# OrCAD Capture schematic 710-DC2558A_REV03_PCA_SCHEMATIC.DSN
size Custom; note: 36V BATTERY CHARGER AND BACKUP MANAGER
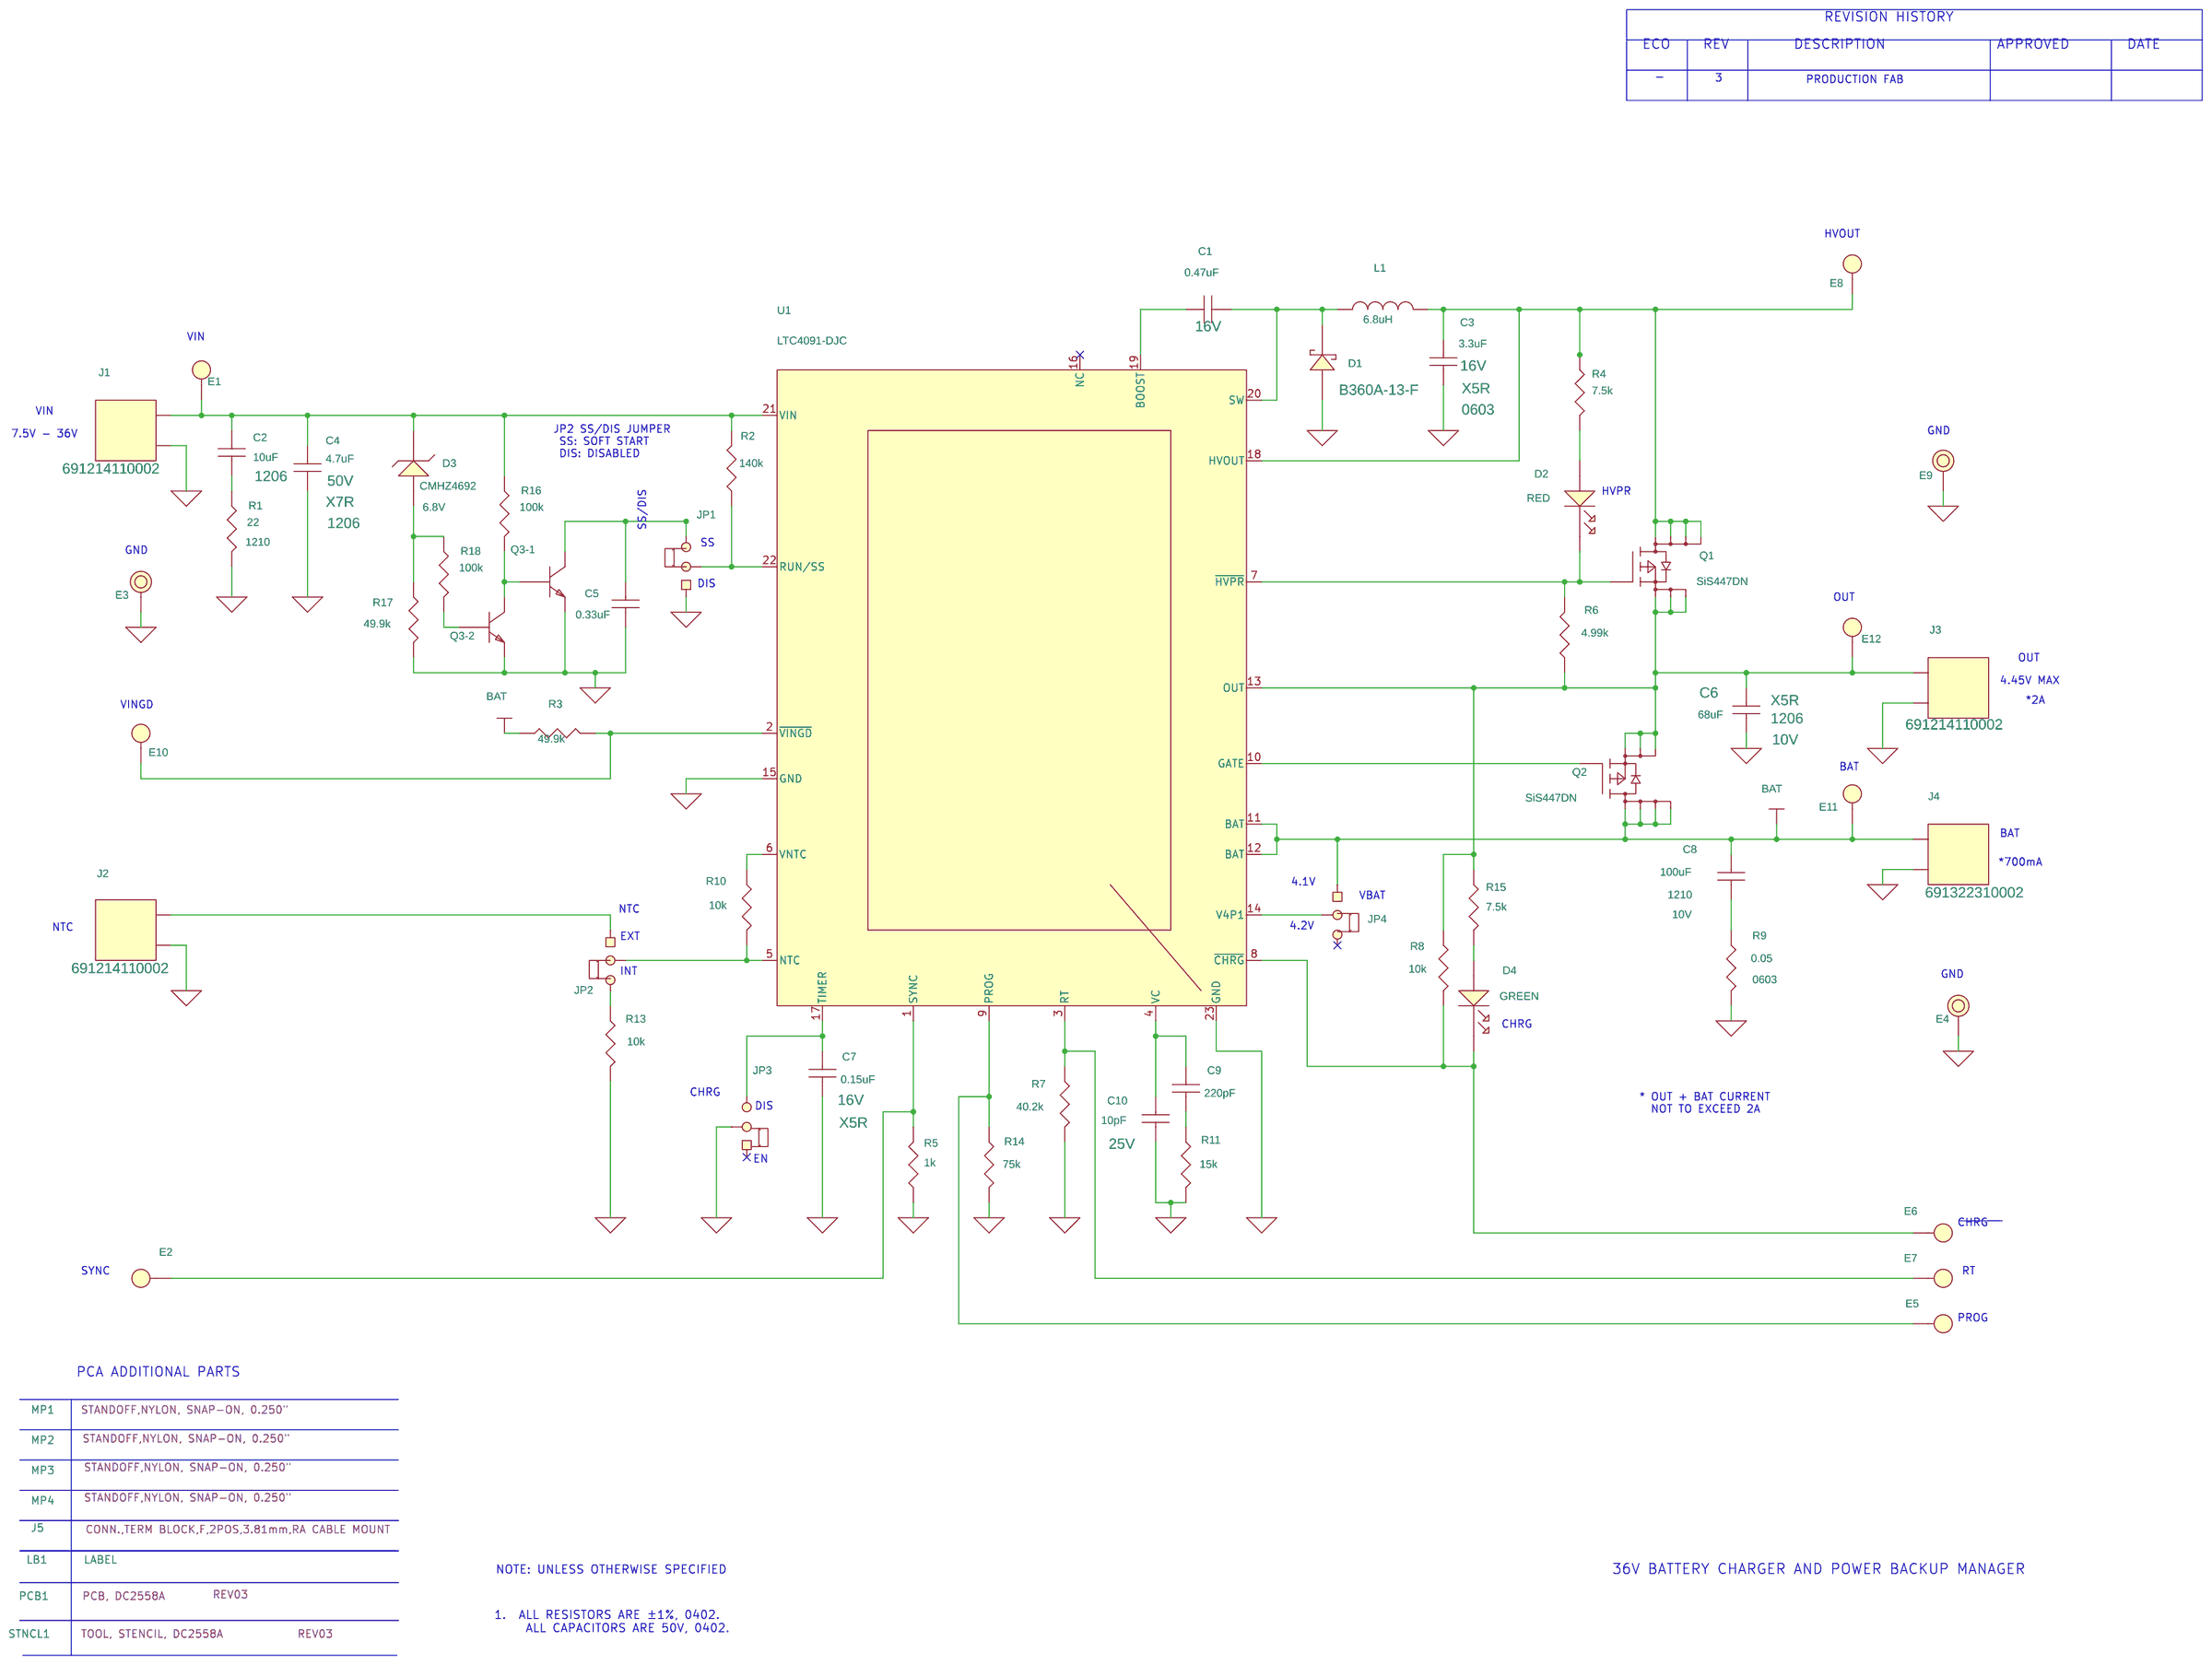
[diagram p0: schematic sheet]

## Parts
C1  0.47uF  [CC0402N]
C2  10uF  [CC1206N]
C3  3.3uF  [CC0603N]
C4  4.7uF  [CC1206N]
C5  0.33uF  [CC0805N]
C6  68uF  [CC1206N]
C7  0.15uF  [CC0402N]
C8  100uF  [CC1210M]
C9  220pF  [CC0402N]
C10  10pF  [CC0402N]
D1  DIODE_SCHOTTKY_A_ALT  [SMA-N]
D2  RED  [LED-WURTH-WL-SMCW]
D3  CMHZ4692  [SOD-123M]
D4  GREEN  [LED-WURTH-WL-SMCW]
E1  TEST POINT  [MILLMAX2308]
E2  TEST POINT  [MILLMAX2308]
E3  TEST POINT  [MILLMAX2501]
E4  TEST POINT  [MILLMAX2501]
E5  TEST POINT  [MILLMAX2308]
E6  TEST POINT  [MILLMAX2308]
E7  TEST POINT  [MILLMAX2308]
E8  TEST POINT  [MILLMAX2308]
E9  TEST POINT  [MILLMAX2501]
E10  TEST POINT  [MILLMAX2308]
E11  TEST POINT  [MILLMAX2308]
E12  TEST POINT  [MILLMAX2308]
J1  TERMINAL BLOCK  [TERM_BLK-WURTH-691214110002]
J2  TERMINAL BLOCK  [TERM_BLK-WURTH-691214110002]
J3  TERMINAL BLOCK  [TERM_BLK-WURTH-691214110002]
J4  SHROUDED HEADER  [WURTH-691322310002]
J5  TERM BLOCK
JP1  HDR  [HD1X3-079]
JP2  HDR  [HD1X3-079]
JP3  HDR  [HD1X3-079]
JP4  HDR  [HD1X3-079]
L1  6.8uH  [IND-XAL40XX]
LB1  LABEL  [895-0154_REV01]
MP1  STANDOFF  [MTG-8831]
MP2  STANDOFF  [MTG-8831]
MP3  STANDOFF  [MTG-8831]
MP4  STANDOFF  [MTG-8831]
PCB1  PCB, DC2558A
Q1  SiS447DN  [POWERPAK1212-8S]
Q2  SiS447DN  [POWERPAK1212-8S]
Q3  MMDT5551  [DIODESINC-SOT363]  (sections -1,-2)
R1  22  [CR1210N]
R2  140k  [CR0402N]
R3  49.9k  [CR0402N]
R4  7.5k  [CR0402N]
R5  1k  [CR0402N]
R6  4.99k  [CR0402N]
R7  40.2k  [CR0402N]
R8  10k  [CR0402N]
R9  0.05  [CR0603M]
R10  10k  [CR0402N]
R11  15k  [CR0402N]
R13  10k  [CR0402N]
R14  75k  [CR0402N]
R15  7.5k  [CR0402N]
R16  100k  [CR0402N]
R17  49.9k  [CR0402N]
R18  100k  [CR0402N]
STNCL1  TOOL, STENCIL, 700-DC2558A
U1  LTC4091-DJC  [LTC-DJC-22-1714]
XJP1  SHUNT
XJP2  SHUNT
XJP3  SHUNT
XJP4  SHUNT

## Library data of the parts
C1 = CAP: CAP.,0.47uF,X5R,16V,10%,0402; CLASS: DISCRETE; Dielectric Type: X5R; FPLIST: CC0402N,CC0402L,CC0402M; Manufacturer: TAIYO YUDEN; Manufacturer PN: EMK105ABJ474KV-F; PART_NUMBER: 150-3431; Package Size: 0402; Rated Voltage: 16V; Tolerance: 10%
C2 = CAP: CAP.,10uF,X5R,50V,10%,1206; CLASS: DISCRETE; Dielectric Type: X5R; FPLIST: CC1206N,CC1206L,CC1206M; Manufacturer: MURATA; Manufacturer PN: GRM31CR61H106KA12L; PART_NUMBER: 150-0330; Package Size: 1206; Rated Voltage: 50V; Tolerance: 10%
C3 = CAP: CAP.,3.3uF,X5R,16V,10%,0603; CLASS: DISCRETE; Dielectric Type: X5R; Manufacturer: TDK; Manufacturer PN: C1608X5R1C335K080AC; PART_NUMBER: 150-3529; Package Size: 0603; Rated Voltage: 16V; Tolerance: 10%
C4 = CAP: CAP.,4.7uF,X7R,50V,10%,1206; CLASS: DISCRETE; Dielectric Type: X7R; Manufacturer: AVX; Manufacturer PN: 12065C475KAT2A; PART_NUMBER: 150-0334; Package Size: 1206; Package Type: SMD; Rated Voltage: 50V; Tolerance: 10%
C5 = CAP: CAP.,0.33uF,X7R,50V,10%,0805; CLASS: DISCRETE; Dielectric Type: X7R; Manufacturer: MURATA; Manufacturer PN: GCM219R71H334KA55D; PART_NUMBER: 150-0600; Package Size: 0805; Rated Voltage: 50V; Tolerance: 10%
C6 = CAP: CAP.,68uF,X5R,10V,20%,1206; CLASS: DISCRETE; Dielectric Type: X5R; Manufacturer: TDK; Manufacturer PN: C3216X5R1A686M160AC; PART_NUMBER: 150-0601; Package Size: 1206; Package Type: SMD; Rated Voltage: 10V; Tolerance: 20%
C7 = CAP: CAP.,0.15uF,X5R,16V,+/-20%,0402; CLASS: DISCRETE; Dielectric Type: X5R; Manufacturer: TDK; Manufacturer PN: C1005X5R1C154M050BB; PART_NUMBER: 150-0602; Package Size: 0402; Rated Voltage: 16V; Tolerance: +/-20%
C8 = CAP: CAP.,100uF,X5R,10V,20%,1210; CLASS: DISCRETE; Dielectric Type: X5R; FPLIST: CC1210N,CC1210L,CC1210M; Manufacturer: MURATA; Manufacturer PN: GRM32ER61A107ME20L; PART_NUMBER: 150-3207; Package Size: 1210; Rated Voltage: 10V; Tolerance: 20%
C9 = CAP: CAP.,220pF,C0G,50V,5%,0402; CLASS: DISCRETE; Dielectric Type: C0G; Manufacturer: AVX; Manufacturer PN: 04025A221JAT2A; PART_NUMBER: 150-2013; Package Size: 0402; Rated Voltage: 50V; Tolerance: 5%
C10 = CAP: CAP.,10pF,NP0,25V,10%,0402; CLASS: DISCRETE; Dielectric Type: NP0; Manufacturer: AVX; Manufacturer PN: 04023A100KAT2A; PART_NUMBER: 150-3187; Package Size: 0402; Rated Voltage: 25V; Tolerance: 10%
D1 = DIODE_SCHOTTKY_A_ALT: DIODE,SCHOTTKY RECTIFIER,60V,3A,4.6mm X 2.92mm; CLASS: DISCRETE; Manufacturer: DIODES INC.; Manufacturer PN: B360A-13-F; PART_NUMBER: 210-0103; Rated Voltage: 60V
D2 = LED_ALT: LED,RED,WATERCLEAR,1206; CLASS: DISCRETE; FPLIST: LED_1206,LED-WURTH-WL-SMCW; Manufacturer: WURTH ELEKTRONIK; Manufacturer PN: 150120RS75000; PART_NUMBER: 270-0078
D3 = ZENER_DIODE_ALT: DIODE,ZENER,6.8V,500mW,SOD-123; CLASS: DISCRETE; FPLIST: SOD-123N, SOD-123M; Manufacturer: CENTRAL SEMI; Manufacturer PN: CMHZ4692 BK Lead Free; PART_NUMBER: 210-0252; Rated Voltage: 6.8V
D4 = LED_ALT: LED,GREEN,WATERCLEAR,1206; CLASS: DISCRETE; FPLIST: LED_1206,LED-WURTH-WL-SMCW; Manufacturer: WURTH ELEKTRONIK; Manufacturer PN: 150120GS75000; PART_NUMBER: 270-0080
E1 E2 E5-E8 E10-E12 = TEST_POINT_.156_MILL-MAX_2308: TEST POINT,TURRET,0.064",MTG. HOLE; CLASS: IO; Manufacturer: MILL-MAX; Manufacturer PN: 2308-2-00-80-00-00-07-0; PART_NUMBER: 260-0004
E3 E4 E9 = TESTPOINT_.219_MILL-MAX_2501: TEST POINT,TURRET,0.094",MTG. HOLE; CLASS: IO; Manufacturer: MILL-MAX; Manufacturer PN: 2501-2-00-80-00-00-07-0; PART_NUMBER: 260-0003
J1-J3 = 2P_TERMINAL_BLOCK_3.5MM: CONN.,TERMINAL BLOCK,1x2,3.5mm,THT; CLASS: IO; Manufacturer: WURTH ELEKTRONIK; Manufacturer PN: 691214110002; PART_NUMBER: 250-0587
J4 = 2P_TERMINAL_BLOCK_3.5MM: CONN.,SHROUDED HEADER,1x2,3.81mm,THT; CLASS: IO; Manufacturer: WURTH ELEKTRONIK; Manufacturer PN: 691322310002; PART_NUMBER: 250-0690
J5 = BLANK_PINLESS_MECHANICAL_PART: CONN.,TERM BLOCK,F,2POS,3.81mm,RA CABLE MOUNT; CLASS: IO; Manufacturer: WURTH ELEKTRONIK; Manufacturer PN: 691361300002; PART_NUMBER: 250-0691
JP1-JP4 = 3_PIN_HEADER_.079_SINGLE_ROW_D: CONN.,HDR,MALE,1x3,2mm,THT, STR; CLASS: IO; Manufacturer: Wurth Elektronik; Manufacturer PN: 62000311121; PART_NUMBER: 250-0484
L1 = IND_ALT: IND.,6.8uH,PWR,20%,3.9A,74.1mOHMS,SMD 4x4mm; CLASS: DISCRETE; Manufacturer: COILCRAFT; Manufacturer PN: XAL4030-682MEC; PART_NUMBER: 200-0207; Package Size: SMD 4x4mm; Tolerance: 20%
LB1 = BLANK_LABEL: LABEL SPEC, DEMO BOARD SERIAL NUMBER; Manufacturer: BRADY; Manufacturer PN: THT-96-717-10; PART_NUMBER: 895-0154
MP1-MP4 = BLANK_MECHANICAL_PART: STANDOFF,NYLON, SNAP-ON, 0.250"; CLASS: MECHANICAL PART; Manufacturer: KEYSTONE; Manufacturer PN: 8831; PART_NUMBER: 763-0006
PCB1 = BLANK_PCB_PART: BOM Notes: REV03; CLASS: PCB; Manufacturer: EAGLE ELECTRONICS, INC; Manufacturer PN: 600-DC2558A; PART_NUMBER: 600-DC2558A
Q1 Q2 = SiS447DN: XSTR.,MOSFET P-CHAN,20V,17A,8-pin PowerPAK 1212; CLASS: DISCRETE; Manufacturer: VISHAY; Manufacturer PN: SIS447DN-T1-GE3; PART_NUMBER: 240-0200; Package Size: 3.33mmx3.33mm; Package Type: 8-pin PowerPAK 1212
Q3 = MMDT5551_SOT-363_ALT: XSTR.,GP BJT NPN,160V,0.2A,SOT-363; CLASS: DISCRETE; Manufacturer: DIODES, INC.; Manufacturer PN: MMDT5551-7-F; PART_NUMBER: 240-0261; Package Size: SOT-363; Package Type: SOT-363
R1 = RES: RES.,22 OHMS,1%,1/2W,1210; CLASS: DISCRETE; Manufacturer: VISHAY; Manufacturer PN: CRCW121022R0FKEA; PART_NUMBER: 100-2045; Package Size: 1210; Rated Power: 1/2W; Temperature Coefficient: 100PPM; Tolerance: 1%
R2 = RES: RES.,140k OHMS,1%,1/16W,0402; CLASS: DISCRETE; Manufacturer: VISHAY; Manufacturer PN: CRCW0402140KFKED; PART_NUMBER: 100-2880; Package Size: 0402; Rated Power: 1/16W; Temperature Coefficient: 100ppm; Tolerance: 1%
R3 R17 = RES: RES.,49.9k OHMS,1%,1/16W,0402; CLASS: DISCRETE; Manufacturer: NIC; Manufacturer PN: NRC04F4992TRF; PART_NUMBER: 100-2406; Package Size: 0402; Rated Power: 1/16W; Temperature Coefficient: 100ppm/C; Tolerance: 1%
R4 R15 = RES: RES.,7.5k OHMS,10%,1/16W,0402; CLASS: DISCRETE; FPLIST: CR0402N,CR0402L,CR0402M; Manufacturer: VISHAY; Manufacturer PN: CRCW04027K50FKED; PART_NUMBER: 100-2038; Package Size: 0402; Rated Power: 1/16W; Temperature Coefficient: 100+/-; Tolerance: 10%
R5 = RES: RES.,1k OHM,1%,1/16W,0402; CLASS: DISCRETE; Manufacturer: VISHAY; Manufacturer PN: CRCW04021K00FKED; PART_NUMBER: 100-2456; Package Size: 0402; Rated Power: 1/16W; Temperature Coefficient: 100ppm/C; Tolerance: 1%
R6 = RES: RES.,AEC-Q200,4.99k OHMS,1%,1/10W,0402; CLASS: DISCRETE; Manufacturer: PANASONIC; Manufacturer PN: ERJ2RKF4991X; PART_NUMBER: 100-2409; Package Size: 0402; Rated Power: 1/10W; Temperature Coefficient: 100ppm/C; Tolerance: 1%
R7 = RES: RES.,40.2k OHMS,1%,1/16W,0402; CLASS: DISCRETE; Manufacturer: NIC; Manufacturer PN: NRC04F4022TRF; PART_NUMBER: 100-0296; Package Size: 0402; Rated Power: 1/16W; Temperature Coefficient: 100ppm; Tolerance: 1%
R8 = RES: RES.,10k OHMS,1%,1/16W,0402; CLASS: DISCRETE; FPLIST: CR0402N,CR0402L,CR0402M; Manufacturer: VISHAY; Manufacturer PN: CRCW040210K0FKED; PART_NUMBER: 100-2545; Package Size: 0402; Rated Power: 1/16W; Temperature Coefficient: 100ppm/C; Tolerance: 1%
R9 = RES: RES.,AEC-Q200,0.05 OHMS,1%,1/4W,0603; CLASS: DISCRETE; FPLIST: CR0603N,CR0603L,CR0603M; Manufacturer: SUSMU; Manufacturer PN: RL0816S-R050-F; PART_NUMBER: 100-0808; Package Size: 0603; Rated Power: 1/4W; Temperature Coefficient: +/-100PPM; Tolerance: 1%
R10 R13 = RES: RES.,10k OHMS,1%,1/16W,0402; CLASS: DISCRETE; Manufacturer: VISHAY; Manufacturer PN: CRCW040210K0FKED; PART_NUMBER: 100-2545; Package Size: 0402; Rated Power: 1/16W; Temperature Coefficient: 100ppm/C; Tolerance: 1%
R11 = RES: RES.,15k OHMS,1%,1/16W,0402; CLASS: DISCRETE; Manufacturer: NIC; Manufacturer PN: NRC04F1502TRF; PART_NUMBER: 100-2315; Package Size: 0402; Rated Power: 1/16W; Temperature Coefficient: 100ppm/C; Tolerance: 1%
R14 = RES: RES.,75k OHMS,1%,1/16W,0402; CLASS: DISCRETE; Manufacturer: VISHAY; Manufacturer PN: CRCW040275K0FKED; PART_NUMBER: 100-0536; Package Size: 0402; Rated Power: 1/16W; Temperature Coefficient: 100ppm; Tolerance: 1%
R16 R18 = RES: RES.,100k OHMS,1%,1/16W,0402; CLASS: DISCRETE; Manufacturer: VISHAY; Manufacturer PN: CRCW0402100KFKED; PART_NUMBER: 100-2396; Package Size: 0402; Rated Power: 1/16W; Temperature Coefficient: 100ppm; Tolerance: 1%
STNCL1 = BLANK_STENCIL_PART: TOOL, STENCIL, DC2558A; BOM Notes: REV03; CLASS: DISCRETE; Manufacturer: LINEAR TECHNOLOGY; Manufacturer PN: 830-DC2558A; PART_NUMBER: 830-2558A
U1 = LTC4091-DJC: IC,36V BAT.CHARGER & BACKUP,22-pin DFN; CLASS: IC; Manufacturer: LINEAR TECHNOLOGY; Manufacturer PN: LTC4091EDJC#PBF; PART_NUMBER: LTC4091EDJC#PBF; Package Type: 22-pin DFN
XJP1-XJP4 = CONN_SHUNT_2_POS_2mm: CONN.,SHUNT,FEMALE,2 POS,2mm; CLASS: IO; Manufacturer: Wurth Elektronik; Manufacturer PN: 60800213421; PART_NUMBER: 250-0485

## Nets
GND_SIGNAL: C3.2 C4.2 C5.2 C6.2 C7.2 C10.2 D1.2(A) E3.1 E4.1 E9.1 J1.2 J2.2 J3.1 J4.1 JP1.1 JP3.2 Q3.1(E) Q3.4(E) R1.2 R5.2 R7.2 R9.2 R11.2 R13.2 R14.2 R17.2 U1.15(GND) U1.23(GND)
BAT: C8.1 E11.1(A) J4.2 JP4.1 Q2.5(D) Q2.6(Dtab) Q2.7(Dtab1) Q2.8(Dtab2) R3.1 U1.11(BAT) U1.12(BAT)
N16773564: JP2.2 R10.2 U1.5(NTC)
N16773568: JP2.3 R13.1
N16773622: C2.1 C4.1 D3.1(C) E1.1(A) J1.1 R2.2 R16.1 U1.21(VIN)
N16773728: C3.1 E8.1(A) L1.2 Q1.5(D) Q1.6(Dtab) Q1.7(Dtab1) Q1.8(Dtab2) R4.2 U1.18(HVOUT)
N16773818: C6.1 E12.1(A) J3.2 Q1.1(S) Q1.2(Stab) Q1.3(Stab1) Q2.1(S) Q2.2(Stab) Q2.3(Stab1) R6.1 R8.1 R15.1 U1.13(OUT)
N16773994: J2.1 JP2.1
N16774122: C2.2 R1.1
N16774242: E5.1(A) R14.1 U1.9(PROG)
N16774266: D4.2(ANODE) R15.2
N16774456: C1.2 D1.1(C) L1.1 U1.20(SW)
N16774618: C1.1 U1.19(BOOST)
N16774720: C8.2 R9.1
N16774858: R10.1 U1.6(VNTC)
N16774890: C9.1 C10.1 U1.4(VC)
N16790279: D2.2(ANODE) R4.1
N16790296: D2.1(CATHODE) Q1.4(G) R6.2 U1.7(~{HVPR})
N16792114: E2.1(A) R5.1 U1.1(SYNC)
N16794685: C7.1 JP3.3 U1.17(TIMER)
N16794767: E7.1(A) R7.1 U1.3(RT)
N16812968: D4.1(CATHODE) E6.1(A) R8.2 U1.8(~{CHRG})
N16840013: C5.1 JP1.3 Q3.6(C)
N16841603: Q3.2(B) Q3.3(C) R16.2
N16841736: Q3.5(B) R18.2
N16841932: D3.2(A) R17.1 R18.1
N16859187: JP1.2 R2.1 U1.22(RUN/SS)
N16879948: C9.2 R11.1
N16885293: E10.1(A) R3.2 U1.2(~{VINGD})
N16900817: JP4.2 U1.14(V4P1)
N16900823: Q2.4(G) U1.10(GATE)

Not connected (* = marked no-connect by the designer): JP3 1*; JP4 3*; U1 16(NC)*

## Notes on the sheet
- REVISION HISTORY
- ECO
- REV
- DESCRIPTION
- APPROVED
- DATE
- -
- 3
- PRODUCTION FAB
- HVOUT
- VIN
- VIN
- 7.5V - 36V
- JP2 SS/DIS JUMPER
   SS: SOFT START
   DIS: DISABLED
- GND
- HVPR
- SS/DIS
- GND
- SS
- DIS
- OUT
- OUT
- 4.45V MAX
- VINGD
- *2A
- BAT
- BAT
- *700mA
- 4.1V
- NTC
- VBAT
- NTC
- 4.2V
- EXT
- INT
- GND
- CHRG
- CHRG
- DIS
- * OUT + BAT CURRENT
    NOT TO EXCEED 2A
- EN
- CHRG
- SYNC
- RT
- PROG
- PCA ADDITIONAL PARTS
- NOTE: UNLESS OTHERWISE SPECIFIED
- 36V BATTERY CHARGER AND POWER BACKUP MANAGER
- 1.  ALL RESISTORS ARE ±1%, 0402.
       ALL CAPACITORS ARE 50V, 0402.
